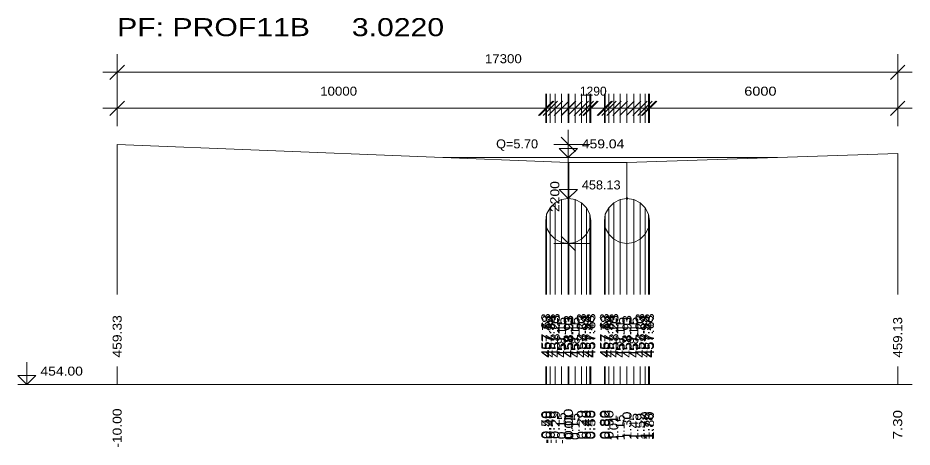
# Model space of a CAD drawing. Extents: x 7 to 442, y -393 to 441.
# Drawn here: x 289.44 to 309.25, y -239.19 to -229.66 of the extents above; entities that cross this region are included whole.
import ezdxf

# ---------------------------------------------------------------- set-up
doc = ezdxf.new("R2010")
doc.units = 0
doc.header["$LTSCALE"] = 0.08
doc.header["$PDMODE"] = 32
doc.header["$PDSIZE"] = 0.04
doc.layers.add('7', color=7, linetype='Continuous', lineweight=13)

msp = doc.modelspace()

# ---------------------------------------------------------------- linework, layer by layer
at = {"layer": '7'}
for p, q in [((291.635, -232.07), (291.635, -230.47)), ((308.935, -232.07), (308.935, -230.47)), ((291.315, -230.87), (309.255, -230.87)), ((291.475, -231.03), (291.795, -230.71)), ((308.775, -231.03), (309.095, -230.71)), ((291.635, -231.99), (291.635, -231.35)), ((301.135, -231.99), (301.135, -231.35)), ((301.155, -231.99), (301.155, -231.35)), ((301.155, -231.99), (301.155, -231.35)), ((301.235, -231.99), (301.235, -231.35)), ((301.235, -231.99), (301.235, -231.35)), ((301.345, -231.99), (301.345, -231.35)), ((301.345, -231.99), (301.345, -231.35)), ((301.485, -231.99), (301.485, -231.35)), ((301.485, -231.99), (301.485, -231.35)), ((301.635, -231.99), (301.635, -231.35)), ((301.635, -231.99), (301.635, -231.35)), ((301.635, -231.99), (301.635, -231.35)), ((301.645, -231.99), (301.645, -231.35)), ((301.645, -231.99), (301.645, -231.35)), ((301.785, -231.99), (301.785, -231.35)), ((301.785, -231.99), (301.785, -231.35)), ((301.925, -231.99), (301.925, -231.35)), ((301.925, -231.99), (301.925, -231.35)), ((302.035, -231.99), (302.035, -231.35)), ((302.035, -231.99), (302.035, -231.35)), ((302.115, -231.99), (302.115, -231.35)), ((302.115, -231.99), (302.115, -231.35)), ((302.135, -231.99), (302.135, -231.35)), ((302.435, -231.99), (302.435, -231.35)), ((302.455, -231.99), (302.455, -231.35)), ((302.455, -231.99), (302.455, -231.35)), ((302.535, -231.99), (302.535, -231.35)), ((302.535, -231.99), (302.535, -231.35)), ((302.645, -231.99), (302.645, -231.35)), ((302.645, -231.99), (302.645, -231.35)), ((302.785, -231.99), (302.785, -231.35)), ((302.785, -231.99), (302.785, -231.35)), ((302.935, -231.99), (302.935, -231.35)), ((302.935, -231.99), (302.935, -231.35)), ((302.935, -231.99), (302.935, -231.35)), ((302.935, -231.99), (302.935, -231.35)), ((302.935, -231.99), (302.935, -231.35)), ((303.085, -231.99), (303.085, -231.35)), ((303.085, -231.99), (303.085, -231.35)), ((303.225, -231.99), (303.225, -231.35)), ((303.225, -231.99), (303.225, -231.35)), ((303.335, -231.99), (303.335, -231.35)), ((303.335, -231.99), (303.335, -231.35)), ((303.415, -231.99), (303.415, -231.35)), ((303.415, -231.99), (303.415, -231.35)), ((303.435, -231.99), (303.435, -231.35)), ((308.935, -231.99), (308.935, -231.35)), ((291.315, -231.67), (309.255, -231.67)), ((291.475, -231.83), (291.795, -231.51)), ((300.975, -231.83), (301.295, -231.51)), ((300.995, -231.83), (301.315, -231.51)), ((300.995, -231.83), (301.315, -231.51)), ((301.075, -231.83), (301.395, -231.51)), ((301.075, -231.83), (301.395, -231.51)), ((301.185, -231.83), (301.505, -231.51)), ((301.185, -231.83), (301.505, -231.51)), ((301.325, -231.83), (301.645, -231.51)), ((301.325, -231.83), (301.645, -231.51)), ((301.475, -231.83), (301.795, -231.51)), ((301.475, -231.83), (301.795, -231.51)), ((301.475, -231.83), (301.795, -231.51)), ((301.485, -231.83), (301.805, -231.51)), ((301.485, -231.83), (301.805, -231.51)), ((301.625, -231.83), (301.945, -231.51)), ((301.625, -231.83), (301.945, -231.51)), ((301.765, -231.83), (302.085, -231.51)), ((301.765, -231.83), (302.085, -231.51)), ((301.875, -231.83), (302.195, -231.51)), ((301.875, -231.83), (302.195, -231.51)), ((301.955, -231.83), (302.275, -231.51)), ((301.955, -231.83), (302.275, -231.51)), ((301.975, -231.83), (302.295, -231.51)), ((302.275, -231.83), (302.595, -231.51)), ((302.295, -231.83), (302.615, -231.51)), ((302.295, -231.83), (302.615, -231.51)), ((302.375, -231.83), (302.695, -231.51)), ((302.375, -231.83), (302.695, -231.51)), ((302.485, -231.83), (302.805, -231.51)), ((302.485, -231.83), (302.805, -231.51)), ((302.625, -231.83), (302.945, -231.51)), ((302.625, -231.83), (302.945, -231.51)), ((302.775, -231.83), (303.095, -231.51)), ((302.775, -231.83), (303.095, -231.51)), ((302.775, -231.83), (303.095, -231.51)), ((302.775, -231.83), (303.095, -231.51)), ((302.775, -231.83), (303.095, -231.51)), ((302.925, -231.83), (303.245, -231.51)), ((302.925, -231.83), (303.245, -231.51)), ((303.065, -231.83), (303.385, -231.51)), ((303.065, -231.83), (303.385, -231.51)), ((303.175, -231.83), (303.495, -231.51)), ((303.175, -231.83), (303.495, -231.51)), ((303.255, -231.83), (303.575, -231.51)), ((303.255, -231.83), (303.575, -231.51)), ((303.275, -231.83), (303.595, -231.51)), ((308.775, -231.83), (309.095, -231.51)), ((301.635, -234.83), (301.635, -232.15)), ((291.635, -235.8), (291.635, -232.47)), ((301.315, -232.47), (302.115, -232.47)), ((301.795, -232.63), (301.475, -232.31)), ((308.935, -235.8), (308.935, -232.67)), ((298.853, -232.759), (306.274, -232.759)), ((301.635, -235.8), (301.635, -232.87)), ((301.645, -235.8), (301.645, -232.87)), ((302.935, -235.8), (302.935, -232.87)), ((302.935, -235.8), (302.935, -232.87)), ((301.635, -235.8), (301.635, -233.67)), ((301.635, -233.67), (301.645, -233.67)), ((301.645, -235.8), (301.645, -233.67)), ((302.935, -235.8), (302.935, -233.67)), ((302.935, -235.8), (302.935, -233.67)), ((301.345, -235.8), (301.345, -233.77)), ((301.485, -235.8), (301.485, -233.69)), ((301.785, -235.8), (301.785, -233.69)), ((301.925, -235.8), (301.925, -233.77)), ((302.645, -235.8), (302.645, -233.77)), ((302.785, -235.8), (302.785, -233.69)), ((303.085, -235.8), (303.085, -233.69)), ((303.225, -235.8), (303.225, -233.77)), ((301.155, -235.8), (301.155, -234.02)), ((301.235, -235.8), (301.235, -233.88)), ((302.035, -235.8), (302.035, -233.88)), ((302.115, -235.8), (302.115, -234.02)), ((302.455, -235.8), (302.455, -234.02)), ((302.535, -235.8), (302.535, -233.88)), ((303.335, -235.8), (303.335, -233.88)), ((303.415, -235.8), (303.415, -234.02)), ((301.135, -235.8), (301.135, -234.17)), ((302.135, -235.8), (302.135, -234.17)), ((302.435, -235.8), (302.435, -234.17)), ((303.435, -235.8), (303.435, -234.17)), ((301.155, -235.8), (301.155, -234.32)), ((301.235, -235.8), (301.235, -234.46)), ((302.035, -235.8), (302.035, -234.46)), ((302.115, -235.8), (302.115, -234.32)), ((302.455, -235.8), (302.455, -234.32)), ((302.535, -235.8), (302.535, -234.46)), ((303.335, -235.8), (303.335, -234.46)), ((303.415, -235.8), (303.415, -234.32)), ((301.345, -235.8), (301.345, -234.57)), ((301.795, -234.83), (301.475, -234.51)), ((301.485, -235.8), (301.485, -234.65)), ((301.785, -235.8), (301.785, -234.65)), ((301.925, -235.8), (301.925, -234.57)), ((302.645, -235.8), (302.645, -234.57)), ((302.785, -235.8), (302.785, -234.65)), ((303.085, -235.8), (303.085, -234.65)), ((303.225, -235.8), (303.225, -234.57)), ((301.315, -234.67), (302.115, -234.67)), ((301.635, -235.8), (301.635, -234.67)), ((302.935, -235.8), (302.935, -234.67)), ((291.635, -237.8), (291.635, -237.4)), ((301.135, -237.8), (301.135, -237.4)), ((301.155, -237.8), (301.155, -237.4)), ((301.155, -237.8), (301.155, -237.4)), ((301.235, -237.8), (301.235, -237.4)), ((301.235, -237.8), (301.235, -237.4)), ((301.345, -237.8), (301.345, -237.4)), ((301.345, -237.8), (301.345, -237.4)), ((301.485, -237.8), (301.485, -237.4)), ((301.485, -237.8), (301.485, -237.4)), ((301.635, -237.8), (301.635, -237.4)), ((301.635, -237.8), (301.635, -237.4)), ((301.635, -237.8), (301.635, -237.4)), ((301.645, -237.8), (301.645, -237.4)), ((301.645, -237.8), (301.645, -237.4)), ((301.785, -237.8), (301.785, -237.4)), ((301.785, -237.8), (301.785, -237.4)), ((301.925, -237.8), (301.925, -237.4)), ((301.925, -237.8), (301.925, -237.4)), ((302.035, -237.8), (302.035, -237.4)), ((302.035, -237.8), (302.035, -237.4)), ((302.115, -237.8), (302.115, -237.4)), ((302.115, -237.8), (302.115, -237.4)), ((302.135, -237.8), (302.135, -237.4)), ((302.435, -237.8), (302.435, -237.4)), ((302.455, -237.8), (302.455, -237.4)), ((302.455, -237.8), (302.455, -237.4)), ((302.535, -237.8), (302.535, -237.4)), ((302.535, -237.8), (302.535, -237.4)), ((302.645, -237.8), (302.645, -237.4)), ((302.645, -237.8), (302.645, -237.4)), ((302.785, -237.8), (302.785, -237.4)), ((302.785, -237.8), (302.785, -237.4)), ((302.935, -237.8), (302.935, -237.4)), ((302.935, -237.8), (302.935, -237.4)), ((302.935, -237.8), (302.935, -237.4)), ((302.935, -237.8), (302.935, -237.4)), ((302.935, -237.8), (302.935, -237.4)), ((303.085, -237.8), (303.085, -237.4)), ((303.085, -237.8), (303.085, -237.4)), ((303.225, -237.8), (303.225, -237.4)), ((303.225, -237.8), (303.225, -237.4)), ((303.335, -237.8), (303.335, -237.4)), ((303.335, -237.8), (303.335, -237.4)), ((303.415, -237.8), (303.415, -237.4)), ((303.415, -237.8), (303.415, -237.4)), ((303.435, -237.8), (303.435, -237.4)), ((308.935, -237.8), (308.935, -237.4)), ((289.435, -237.8), (309.255, -237.8))]:
    msp.add_line(p, q, dxfattribs=at)
for points in [[(301.635, -232.259), (301.635, -232.759), (301.435, -232.559), (301.835, -232.559), (301.635, -232.759)], [(291.635, -232.47), (301.635, -232.87), (301.635, -233.67), (301.485, -233.69), (301.345, -233.77), (301.235, -233.88), (301.155, -234.02), (301.135, -234.17), (301.155, -234.32), (301.235, -234.46), (301.345, -234.57), (301.485, -234.65), (301.635, -234.67), (301.785, -234.65), (301.925, -234.57), (302.035, -234.46), (302.115, -234.32), (302.135, -234.17), (302.115, -234.02), (302.035, -233.88), (301.925, -233.77), (301.785, -233.69), (301.645, -233.67), (301.645, -232.87), (302.935, -232.87), (302.935, -233.67), (302.785, -233.69), (302.645, -233.77), (302.535, -233.88), (302.455, -234.02), (302.435, -234.17), (302.455, -234.32), (302.535, -234.46), (302.645, -234.57), (302.785, -234.65), (302.935, -234.67), (303.085, -234.65), (303.225, -234.57), (303.335, -234.46), (303.415, -234.32), (303.435, -234.17), (303.415, -234.02), (303.335, -233.88), (303.225, -233.77), (303.085, -233.69), (302.935, -233.67), (302.935, -232.87), (308.935, -232.67)], [(301.635, -233.17), (301.635, -233.67), (301.435, -233.47), (301.835, -233.47), (301.635, -233.67)], [(289.635, -237.3), (289.635, -237.8), (289.435, -237.6), (289.835, -237.6), (289.635, -237.8)]]:
    msp.add_lwpolyline(points, dxfattribs=at)
msp.add_point((302.935, -233.67), dxfattribs=at)

# ---------------------------------------------------------------- texts
for s, height, width, p in [('PF: PROF11B     3.0220', 0.4, 1.25, (291.635, -230.07)), ('17300', 0.2, 1.1, (299.785, -230.67)), ('10000', 0.2, 1.1, (296.135, -231.39)), ('6000', 0.2, 1.2, (305.535, -231.39)), ('Q=5.70', 0.2, 1.05, (300.035, -232.559)), ('459.04', 0.2, 1.15, (301.935, -232.559)), ('458.13', 0.2, 1.05, (301.935, -233.47)), ('454.00', 0.2, 1.15, (289.935, -237.6))]:
    msp.add_text(s, height=height, dxfattribs=dict(at, width=width)).set_placement(p)
msp.add_text('1290', height=0.2, dxfattribs=at).set_placement((301.89, -231.39))
for s, width, p in [('2200', 1.15, (301.435, -233.97)), ('457.63 ', 1.2, (301.235, -237.2)), ('458.03 ', 1.2, (301.445, -237.2)), ('458.03 ', 1.2, (302.025, -237.2)), ('457.63 ', 1.2, (302.235, -237.2)), ('457.63 ', 1.2, (302.535, -237.2)), ('458.03 ', 1.2, (302.745, -237.2)), ('458.03 ', 1.2, (303.325, -237.2)), ('457.63 ', 1.2, (303.535, -237.2)), ('459.33 ', 1.15, (291.735, -237.2)), ('457.78 ', 1.15, (301.255, -237.2)), ('457.48 ', 1.15, (301.255, -237.2)), ('457.34 ', 1.15, (301.335, -237.2)), ('457.92 ', 1.15, (301.335, -237.2)), ('457.23 ', 1.15, (301.445, -237.2)), ('457.15 ', 1.1, (301.585, -237.2)), ('458.93 ', 1.15, (301.735, -237.2)), ('458.13 ', 1.1, (301.735, -237.2)), ('457.13 ', 1.1, (301.735, -237.2)), ('458.93 ', 1.15, (301.745, -237.2)), ('458.13 ', 1.1, (301.745, -237.2)), ('457.15 ', 1.1, (301.885, -237.2)), ('457.23 ', 1.15, (302.025, -237.2)), ('457.34 ', 1.15, (302.135, -237.2)), ('457.92 ', 1.15, (302.135, -237.2)), ('457.48 ', 1.15, (302.215, -237.2)), ('457.78 ', 1.15, (302.215, -237.2)), ('457.78 ', 1.15, (302.555, -237.2)), ('457.48 ', 1.15, (302.555, -237.2)), ('457.34 ', 1.15, (302.635, -237.2)), ('457.92 ', 1.15, (302.635, -237.2)), ('457.23 ', 1.15, (302.745, -237.2)), ('457.15 ', 1.1, (302.885, -237.2)), ('458.93 ', 1.15, (303.035, -237.2)), ('458.93 ', 1.15, (303.035, -237.2)), ('458.13 ', 1.1, (303.035, -237.2)), ('457.13 ', 1.1, (303.035, -237.2)), ('458.13 ', 1.1, (303.035, -237.2)), ('457.15 ', 1.1, (303.185, -237.2)), ('457.23 ', 1.15, (303.325, -237.2)), ('457.34 ', 1.15, (303.435, -237.2)), ('457.92 ', 1.15, (303.435, -237.2)), ('457.48 ', 1.15, (303.515, -237.2)), ('457.78 ', 1.15, (303.515, -237.2)), ('459.13 ', 1.1, (309.035, -237.2)), ('-10.00 ', 1.15, (291.735, -239.2)), (' -0.50 ', 1.2, (301.235, -239.2)), (' -0.48 ', 1.2, (301.255, -239.2)), (' -0.48 ', 1.2, (301.255, -239.2)), (' -0.40 ', 1.2, (301.335, -239.2)), (' -0.40 ', 1.2, (301.335, -239.2)), (' -0.29 ', 1.2, (301.445, -239.2)), (' -0.29 ', 1.2, (301.445, -239.2)), (' -0.15 ', 1.15, (301.585, -239.2)), (' -0.15 ', 1.15, (301.585, -239.2)), ('  0.00 ', 1.3, (301.735, -239.2)), ('  0.00 ', 1.3, (301.735, -239.2)), ('  0.00 ', 1.3, (301.735, -239.2)), ('  0.29 ', 1.25, (302.025, -239.2)), ('  0.29 ', 1.25, (302.025, -239.2)), ('  0.40 ', 1.25, (302.135, -239.2)), ('  0.40 ', 1.25, (302.135, -239.2)), ('  0.48 ', 1.25, (302.215, -239.2)), ('  0.48 ', 1.25, (302.215, -239.2)), ('  0.50 ', 1.25, (302.235, -239.2)), ('  0.80 ', 1.25, (302.535, -239.2)), ('  0.82 ', 1.25, (302.555, -239.2)), ('  0.82 ', 1.25, (302.555, -239.2)), ('  0.90 ', 1.25, (302.635, -239.2)), ('  0.90 ', 1.25, (302.635, -239.2)), ('  1.30 ', 1.2, (303.035, -239.2)), ('  1.30 ', 1.2, (303.035, -239.2)), ('  1.30 ', 1.2, (303.035, -239.2)), ('  1.30 ', 1.2, (303.035, -239.2)), ('  1.30 ', 1.2, (303.035, -239.2)), ('  1.70 ', 1.2, (303.435, -239.2)), ('  1.70 ', 1.2, (303.435, -239.2)), ('  1.80 ', 1.2, (303.535, -239.2)), ('  7.30 ', 1.25, (309.035, -239.2)), ('  0.01 ', 1.15, (301.745, -239.2)), ('  0.01 ', 1.15, (301.745, -239.2)), ('  0.15 ', 1.15, (301.885, -239.2)), ('  0.15 ', 1.15, (301.885, -239.2)), ('  1.01 ', 1.05, (302.745, -239.2)), ('  1.01 ', 1.05, (302.745, -239.2)), ('  1.15 ', 1.1, (302.885, -239.2)), ('  1.15 ', 1.1, (302.885, -239.2)), ('  1.45 ', 1.15, (303.185, -239.2)), ('  1.45 ', 1.15, (303.185, -239.2)), ('  1.59 ', 1.15, (303.325, -239.2)), ('  1.59 ', 1.15, (303.325, -239.2)), ('  1.78 ', 1.15, (303.515, -239.2)), ('  1.78 ', 1.15, (303.515, -239.2))]:
    msp.add_text(s, height=0.2, rotation=90, dxfattribs=dict(at, width=width)).set_placement(p)
for p in [(301.585, -237.2), (301.885, -237.2), (302.885, -237.2), (303.185, -237.2)]:
    msp.add_text('458.11 ', height=0.2, rotation=90, dxfattribs=at).set_placement(p)

doc.saveas('drawing.dxf')
